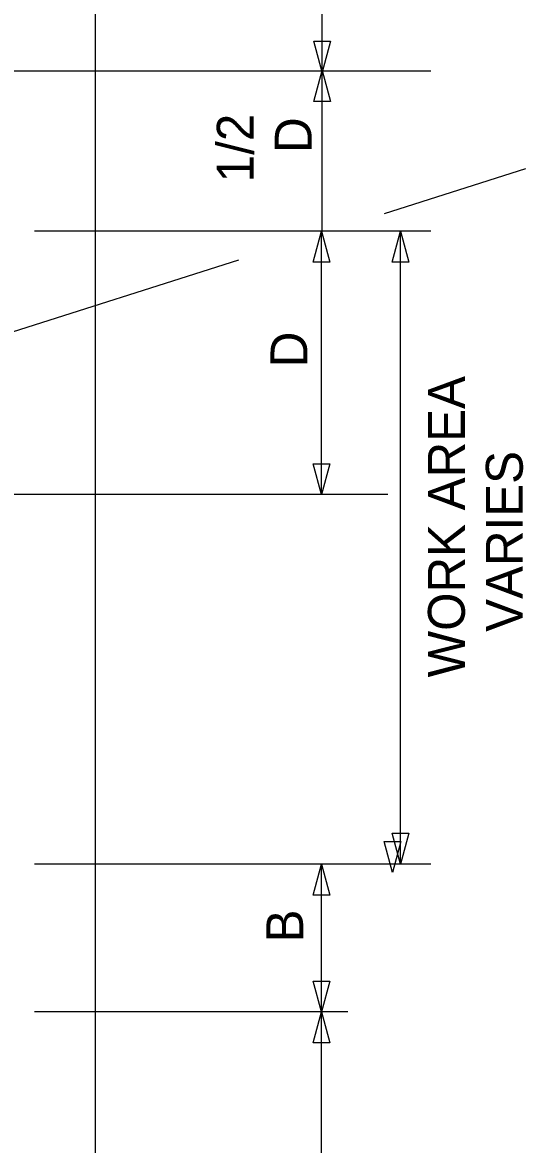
# Model space of a CAD drawing. Extents: x 16038 to 19504, y 5920 to 8321.
# Drawn here: x 17156.5 to 17252, y 7491.1 to 7704.1 of the extents above; entities that cross this region are included whole.
import ezdxf

# ---------------------------------------------------------------- set-up
doc = ezdxf.new("R2010")
doc.units = 0
doc.layers.add('PAVT_EDGE_EX', color=7, linetype='Continuous')
doc.layers.add('TYPICAL_TEXT_DIMEN_PR', color=7, linetype='Continuous')

msp = doc.modelspace()

# ---------------------------------------------------------------- linework, layer by layer
at = {"layer": 'PAVT_EDGE_EX'}
msp.add_line((17170.3, 8211.6), (17170.3, 7367.79), dxfattribs=at)
at = {"layer": 'TYPICAL_TEXT_DIMEN_PR'}
for p, q in [((17213.38, 7695.24), (17213.38, 7788.67)), ((17213.38, 7694.72), (17211.81, 7700.58)), ((17211.81, 7700.58), (17213.38, 7700.58)), ((17213.38, 7700.58), (17214.95, 7700.58)), ((17214.95, 7700.58), (17213.38, 7694.72)), ((17234.03, 7694.89), (17040.97, 7694.89)), ((17211.81, 7689.15), (17213.38, 7695.01)), ((17213.37, 7664.73), (17213.37, 7694.63)), ((17213.38, 7695.01), (17214.95, 7689.15)), ((17213.38, 7689.15), (17211.81, 7689.15)), ((17214.95, 7689.15), (17213.38, 7689.15)), ((17251.99, 7676.33), (17225.13, 7667.8)), ((17234.03, 7664.5), (17158.75, 7664.5)), ((17211.68, 7658.64), (17213.25, 7664.5)), ((17213.25, 7614.5), (17213.25, 7664.5)), ((17213.25, 7664.5), (17214.82, 7658.64)), ((17226.68, 7658.64), (17228.25, 7664.5)), ((17228.25, 7544.33), (17228.25, 7664.5)), ((17228.25, 7664.5), (17229.82, 7658.64)), ((17197.5, 7659.02), (17070.7, 7618.73)), ((17213.25, 7658.64), (17211.68, 7658.64)), ((17214.82, 7658.64), (17213.25, 7658.64)), ((17228.25, 7658.64), (17226.68, 7658.64)), ((17229.82, 7658.64), (17228.25, 7658.64)), ((17213.25, 7614.5), (17211.68, 7620.36)), ((17211.68, 7620.36), (17213.25, 7620.36)), ((17213.25, 7620.36), (17214.82, 7620.36)), ((17214.82, 7620.36), (17213.25, 7614.5)), ((17225.85, 7614.5), (17088.4, 7614.5)), ((17226.71, 7542.75), (17225.14, 7548.61)), ((17225.14, 7548.61), (17226.71, 7548.61)), ((17228.25, 7544.33), (17226.68, 7550.19)), ((17226.68, 7550.19), (17228.25, 7550.19)), ((17226.71, 7548.61), (17228.28, 7548.61)), ((17228.28, 7548.61), (17226.71, 7542.75)), ((17228.25, 7550.19), (17229.82, 7550.19)), ((17229.82, 7550.19), (17228.25, 7544.33)), ((17234.03, 7544.33), (17158.75, 7544.33)), ((17211.68, 7538.47), (17213.25, 7544.33)), ((17213.25, 7516.27), (17213.25, 7544.33)), ((17213.25, 7544.33), (17214.82, 7538.47)), ((17213.25, 7538.47), (17211.68, 7538.47)), ((17214.82, 7538.47), (17213.25, 7538.47)), ((17213.25, 7516.27), (17211.68, 7522.13)), ((17211.68, 7522.13), (17213.25, 7522.13)), ((17213.25, 7522.13), (17214.82, 7522.13)), ((17214.82, 7522.13), (17213.25, 7516.27)), ((17218.25, 7516.27), (17158.75, 7516.27)), ((17211.68, 7510.41), (17213.25, 7516.27)), ((17213.25, 7516.27), (17214.82, 7510.41)), ((17213.25, 7430.79), (17213.25, 7516.27)), ((17213.25, 7510.41), (17211.68, 7510.41)), ((17214.82, 7510.41), (17213.25, 7510.41))]:
    msp.add_line(p, q, dxfattribs=at)

# ---------------------------------------------------------------- texts
for s, p in [('1/2', (17200.37, 7673.8)), ('D', (17211.37, 7679.37)), ('D', (17210.56, 7638.68)), ('WORK AREA', (17240.46, 7579.79)), ('VARIES', (17251.46, 7588.44)), ('B', (17209.78, 7529.47))]:
    msp.add_text(s, height=7, rotation=90, dxfattribs=at).set_placement(p)

doc.saveas('drawing.dxf')
